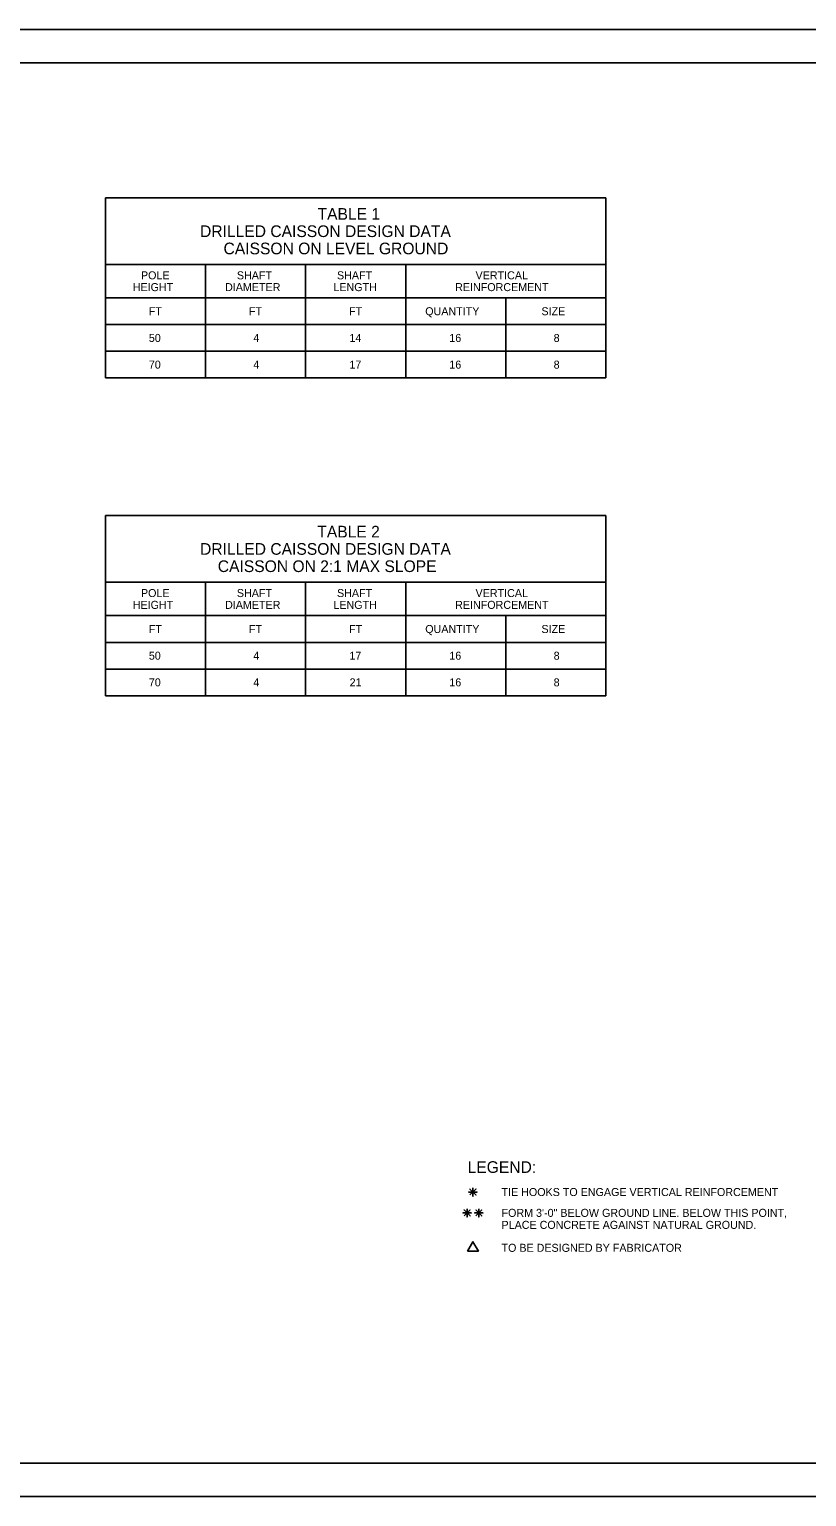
# Model space of a CAD drawing. Extents: x 1299104.6 to 1299141.4, y 239713.3 to 239735.3.
# Drawn here: x 1299116.27 to 1299127.91, y 239713.27 to 239735.27 of the extents above; entities that cross this region are included whole.
import ezdxf

# ---------------------------------------------------------------- set-up
doc = ezdxf.new("R2010")
doc.units = 0
for name, color, linetype in [('DIM TXT', 7, 'Continuous'), ('GS_plotshape_p', 7, 'Continuous'), ('Level 1', 7, 'Continuous'), ('Level 3', 7, 'Continuous'), ('Level 4', 7, 'Continuous')]:
    doc.layers.add(name, color=color, linetype=linetype)

msp = doc.modelspace()

# ---------------------------------------------------------------- linework, layer by layer
at = {"layer": 'DIM TXT'}
for p, q in [((1299122.912, 239717.84), (1299122.912, 239717.84)), ((1299122.825, 239717.527), (1299122.825, 239717.527)), ((1299123, 239717.527), (1299123, 239717.527))]:
    msp.add_line(p, q, dxfattribs=at)
for points in [[(1299122.912, 239717.902), (1299122.912, 239717.777), (1299122.912, 239717.84), (1299122.975, 239717.84), (1299122.85, 239717.84), (1299122.912, 239717.84), (1299122.868, 239717.884), (1299122.957, 239717.796), (1299122.912, 239717.84), (1299122.957, 239717.884), (1299122.868, 239717.796)], [(1299122.825, 239717.59), (1299122.825, 239717.465), (1299122.825, 239717.527), (1299122.887, 239717.527), (1299122.762, 239717.527), (1299122.825, 239717.527), (1299122.781, 239717.571), (1299122.869, 239717.483), (1299122.825, 239717.527), (1299122.869, 239717.571), (1299122.781, 239717.483)], [(1299123, 239717.59), (1299123, 239717.465), (1299123, 239717.527), (1299123.062, 239717.527), (1299122.937, 239717.527), (1299123, 239717.527), (1299122.956, 239717.571), (1299123.044, 239717.483), (1299123, 239717.527), (1299123.044, 239717.571), (1299122.956, 239717.483)]]:
    msp.add_lwpolyline(points, dxfattribs=at)
msp.add_lwpolyline([(1299122.831, 239716.954), (1299122.994, 239716.954), (1299122.912, 239717.095)], close=True, dxfattribs=at)
at = {"layer": 'GS_plotshape_p'}
msp.add_lwpolyline([(1299104.622, 239735.273), (1299138.622, 239735.273), (1299138.622, 239713.273), (1299104.622, 239713.273)], close=True, dxfattribs=at)
at = {"layer": 'Level 1'}
msp.add_lwpolyline([(1299138.122, 239713.773), (1299106.122, 239713.773), (1299106.122, 239734.773), (1299138.122, 239734.773)], close=True, dxfattribs=at)
at = {"layer": 'Level 3'}
for p, q in [((1299117.406, 239730.046), (1299117.406, 239732.746)), ((1299117.406, 239732.746), (1299124.906, 239732.746)), ((1299124.906, 239730.046), (1299124.906, 239732.746)), ((1299117.406, 239731.746), (1299124.906, 239731.746)), ((1299118.906, 239730.046), (1299118.906, 239731.746)), ((1299120.406, 239730.046), (1299120.406, 239731.746)), ((1299121.906, 239730.046), (1299121.906, 239731.746)), ((1299117.406, 239731.246), (1299124.906, 239731.246)), ((1299123.406, 239730.046), (1299123.406, 239731.246)), ((1299117.406, 239730.846), (1299124.906, 239730.846)), ((1299117.406, 239730.046), (1299124.906, 239730.046)), ((1299117.406, 239725.282), (1299117.406, 239727.982)), ((1299117.406, 239727.982), (1299124.906, 239727.982)), ((1299124.906, 239725.282), (1299124.906, 239727.982)), ((1299117.406, 239726.982), (1299124.906, 239726.982)), ((1299118.906, 239725.282), (1299118.906, 239726.982)), ((1299120.406, 239725.282), (1299120.406, 239726.982)), ((1299121.906, 239725.282), (1299121.906, 239726.982)), ((1299117.406, 239726.482), (1299124.906, 239726.482)), ((1299123.406, 239725.282), (1299123.406, 239726.482)), ((1299117.406, 239726.082), (1299124.906, 239726.082)), ((1299117.406, 239725.282), (1299124.906, 239725.282))]:
    msp.add_line(p, q, dxfattribs=at)
at = {"layer": 'Level 4'}
for p, q in [((1299117.406, 239730.446), (1299124.906, 239730.446)), ((1299117.406, 239725.682), (1299124.906, 239725.682))]:
    msp.add_line(p, q, dxfattribs=at)

# ---------------------------------------------------------------- texts
at = {"layer": 'DIM TXT'}
for s, height, p in [('TABLE 1', 0.175, (1299120.585, 239732.418)), ('DRILLED CAISSON DESIGN DATA', 0.175, (1299118.824, 239732.159)), ('CAISSON ON LEVEL GROUND', 0.175, (1299119.176, 239731.9)), ('POLE', 0.12, (1299117.939, 239731.525)), ('SHAFT', 0.12, (1299119.376, 239731.525)), ('SHAFT', 0.12, (1299120.876, 239731.525)), ('VERTICAL', 0.12, (1299122.952, 239731.525)), ('HEIGHT', 0.12, (1299117.816, 239731.348)), ('DIAMETER', 0.12, (1299119.199, 239731.348)), ('LENGTH', 0.12, (1299120.822, 239731.348)), ('REINFORCEMENT', 0.12, (1299122.646, 239731.348)), ('FT', 0.12, (1299118.056, 239730.986)), ('FT', 0.12, (1299119.556, 239730.986)), ('FT', 0.12, (1299121.056, 239730.986)), ('QUANTITY', 0.12, (1299122.198, 239730.986)), ('SIZE', 0.12, (1299123.939, 239730.986)), ('50', 0.12, (1299118.057, 239730.586)), ('4', 0.12, (1299119.622, 239730.586)), ('14', 0.12, (1299121.062, 239730.586)), ('16', 0.12, (1299122.559, 239730.586)), ('8', 0.12, (1299124.122, 239730.586)), ('70', 0.12, (1299118.057, 239730.186)), ('4', 0.12, (1299119.622, 239730.186)), ('17', 0.12, (1299121.062, 239730.186)), ('16', 0.12, (1299122.559, 239730.186)), ('8', 0.12, (1299124.122, 239730.186)), ('TABLE 2', 0.175, (1299120.581, 239727.654)), ('DRILLED CAISSON DESIGN DATA', 0.175, (1299118.824, 239727.395)), ('CAISSON ON 2:1 MAX SLOPE', 0.175, (1299119.09, 239727.136)), ('POLE', 0.12, (1299117.939, 239726.761)), ('SHAFT', 0.12, (1299119.376, 239726.761)), ('SHAFT', 0.12, (1299120.876, 239726.761)), ('VERTICAL', 0.12, (1299122.952, 239726.761)), ('HEIGHT', 0.12, (1299117.816, 239726.584)), ('DIAMETER', 0.12, (1299119.199, 239726.584)), ('LENGTH', 0.12, (1299120.822, 239726.584)), ('REINFORCEMENT', 0.12, (1299122.646, 239726.584)), ('FT', 0.12, (1299118.056, 239726.222)), ('FT', 0.12, (1299119.556, 239726.222)), ('FT', 0.12, (1299121.056, 239726.222)), ('QUANTITY', 0.12, (1299122.198, 239726.222)), ('SIZE', 0.12, (1299123.939, 239726.222)), ('50', 0.12, (1299118.057, 239725.822)), ('4', 0.12, (1299119.622, 239725.822)), ('17', 0.12, (1299121.062, 239725.822)), ('16', 0.12, (1299122.559, 239725.822)), ('8', 0.12, (1299124.122, 239725.822)), ('70', 0.12, (1299118.057, 239725.422)), ('4', 0.12, (1299119.622, 239725.422)), ('21', 0.12, (1299121.065, 239725.422)), ('16', 0.12, (1299122.559, 239725.422)), ('8', 0.12, (1299124.122, 239725.422)), ('LEGEND:', 0.175, (1299122.833, 239718.127)), ('TIE HOOKS TO ENGAGE VERTICAL REINFORCEMENT', 0.12, (1299123.341, 239717.78)), ('FORM 3\'-0" BELOW GROUND LINE. BELOW THIS POINT,', 0.12, (1299123.341, 239717.468)), ('PLACE CONCRETE AGAINST NATURAL GROUND.', 0.12, (1299123.341, 239717.288)), ('TO BE DESIGNED BY FABRICATOR', 0.12, (1299123.341, 239716.944))]:
    msp.add_text(s, height=height, dxfattribs=at).set_placement(p)

doc.saveas('drawing.dxf')
